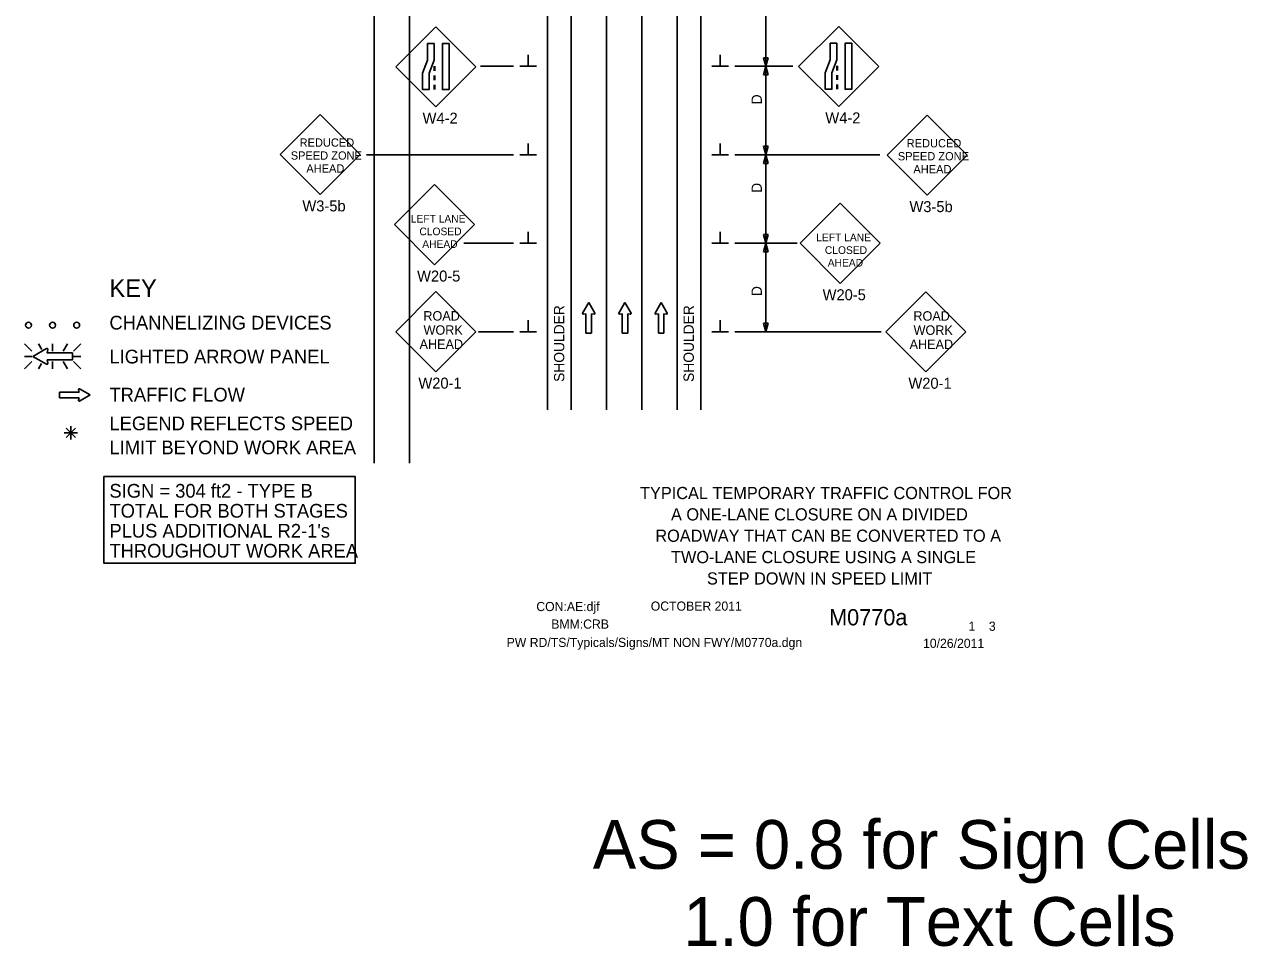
# Model space of a CAD drawing. Extents: x 16744 to 19504, y 5731 to 6974.
# Drawn here: x 16744 to 17573, y 5731 to 6356 of the extents above; entities that cross this region are included whole.
import ezdxf

# ---------------------------------------------------------------- set-up
doc = ezdxf.new("R2010")
doc.units = 0
for name, color, linetype in [('ALI_LEGAL_EX', 7, 'Continuous'), ('BORDER', 7, 'Continuous'), ('BORDER_SIGNAL_WO', 7, 'Continuous'), ('MT_SCRATCH_LEVEL_E', 7, 'Continuous'), ('PAVT_EDGE_EX', 7, 'Continuous'), ('TRAFFIC_SIGNS_PR', 7, 'Continuous'), ('TYPICAL_TEXT_DIMEN_EX', 7, 'Continuous'), ('TYPICAL_TEXT_DIMEN_PR', 7, 'Continuous')]:
    doc.layers.add(name, color=color, linetype=linetype)

msp = doc.modelspace()

# ---------------------------------------------------------------- linework, layer by layer
at = {"layer": 'ALI_LEGAL_EX'}
for p, q in [((16980.68, 6974.12), (16980.68, 6155.98)), ((17004.68, 6974.12), (17004.68, 6155.98)), ((16980.68, 6922.21), (16980.68, 6058.3)), ((17004.68, 6922.21), (17004.68, 6058.3)), ((17138.25, 6923.7), (17138.25, 6094.51)), ((17162.25, 6923.7), (17162.25, 6094.51))]:
    msp.add_line(p, q, dxfattribs=at)
for points in [[(17138.25, 6323.7), (17138.25, 6298.7)], [(17162.25, 6323.7), (17162.25, 6298.7)], [(17138.25, 6223.7), (17138.25, 6198.7)], [(17162.25, 6223.7), (17162.25, 6198.7)], [(17138.25, 6098.7), (17138.25, 6123.7)], [(17138.25, 6098.7), (17138.25, 6123.7)], [(17162.25, 6123.7), (17162.25, 6098.7)]]:
    msp.add_lwpolyline(points, dxfattribs=at)
at = {"layer": 'MT_SCRATCH_LEVEL_E'}
for p, q in [((17126.22, 6167.34), (17122.11, 6160.1)), ((17126.22, 6167.34), (17122.11, 6160.1)), ((17130.37, 6160.1), (17126.22, 6167.34)), ((17130.37, 6160.1), (17126.22, 6167.34)), ((17150.78, 6167.34), (17146.67, 6160.1)), ((17150.78, 6167.34), (17146.67, 6160.1)), ((17154.92, 6160.1), (17150.78, 6167.34)), ((17154.92, 6160.1), (17150.78, 6167.34)), ((17175.34, 6167.34), (17171.22, 6160.1)), ((17175.34, 6167.34), (17171.22, 6160.1)), ((17179.48, 6160.1), (17175.34, 6167.34)), ((17179.48, 6160.1), (17175.34, 6167.34)), ((17122.59, 6159.41), (17124.37, 6159.73)), ((17122.59, 6159.41), (17124.37, 6159.73)), ((17124.37, 6159.73), (17124.37, 6146.47)), ((17124.37, 6159.73), (17124.37, 6146.47)), ((17128.11, 6146.47), (17128.11, 6159.73)), ((17128.11, 6159.73), (17129.89, 6159.41)), ((17128.11, 6146.47), (17128.11, 6159.73)), ((17128.11, 6159.73), (17129.89, 6159.41)), ((17147.15, 6159.41), (17148.92, 6159.73)), ((17147.15, 6159.41), (17148.92, 6159.73)), ((17148.92, 6159.73), (17148.92, 6146.47)), ((17148.92, 6159.73), (17148.92, 6146.47)), ((17152.67, 6146.47), (17152.67, 6159.73)), ((17152.67, 6159.73), (17154.44, 6159.41)), ((17152.67, 6146.47), (17152.67, 6159.73)), ((17152.67, 6159.73), (17154.44, 6159.41)), ((17171.71, 6159.41), (17173.48, 6159.73)), ((17171.71, 6159.41), (17173.48, 6159.73)), ((17173.48, 6159.73), (17173.48, 6146.47)), ((17173.48, 6159.73), (17173.48, 6146.47)), ((17177.23, 6146.47), (17177.23, 6159.73)), ((17177.23, 6159.73), (17179, 6159.41)), ((17177.23, 6146.47), (17177.23, 6159.73)), ((17177.23, 6159.73), (17179, 6159.41)), ((17124.37, 6146.47), (17128.11, 6146.47)), ((17124.37, 6146.47), (17128.11, 6146.47)), ((17148.92, 6146.47), (17152.67, 6146.47)), ((17148.92, 6146.47), (17152.67, 6146.47)), ((17173.48, 6146.47), (17177.23, 6146.47)), ((17173.48, 6146.47), (17177.23, 6146.47)), ((16780.63, 6106.49), (16767.37, 6106.49)), ((16767.37, 6106.49), (16767.37, 6102.75)), ((16780.63, 6106.49), (16767.37, 6106.49)), ((16767.37, 6106.49), (16767.37, 6102.75)), ((16780.31, 6108.27), (16780.63, 6106.49)), ((16780.31, 6108.27), (16780.63, 6106.49)), ((16788.24, 6104.64), (16780.99, 6108.75)), ((16788.24, 6104.64), (16780.99, 6108.75)), ((16780.99, 6100.49), (16788.24, 6104.64)), ((16780.99, 6100.49), (16788.24, 6104.64)), ((16767.37, 6102.75), (16780.63, 6102.75)), ((16767.37, 6102.75), (16780.63, 6102.75)), ((16780.63, 6102.75), (16780.31, 6100.97)), ((16780.63, 6102.75), (16780.31, 6100.97))]:
    msp.add_line(p, q, dxfattribs=at)
for centre, start, end in [((17122.51, 6159.87), 150.42484, 279.96381), ((17122.51, 6159.87), 150.42484, 279.96381), ((17129.96, 6159.87), 260.03619, 29.77312), ((17129.96, 6159.87), 260.03619, 29.77312), ((17147.07, 6159.87), 150.42484, 279.96381), ((17147.07, 6159.87), 150.42484, 279.96381), ((17154.51, 6159.87), 260.03619, 29.77312), ((17154.51, 6159.87), 260.03619, 29.77312), ((17171.63, 6159.87), 150.42484, 279.96381), ((17171.63, 6159.87), 150.42484, 279.96381), ((17179.07, 6159.87), 260.03619, 29.77312), ((17179.07, 6159.87), 260.03619, 29.77312), ((16780.77, 6108.34), 60.42484, 189.96381), ((16780.77, 6108.34), 60.42484, 189.96381), ((16780.77, 6100.9), 170.03619, 299.77312), ((16780.77, 6100.9), 170.03619, 299.77312)]:
    msp.add_arc(centre, 0.463, start, end, dxfattribs=at)
at = {"layer": 'PAVT_EDGE_EX'}
for p, q in [((17098.25, 6923.7), (17098.25, 6094.51)), ((17114.25, 6923.7), (17114.25, 6094.51)), ((17186.25, 6923.7), (17186.25, 6094.51)), ((17202.25, 6923.7), (17202.25, 6094.51))]:
    msp.add_line(p, q, dxfattribs=at)
at = {"layer": 'TRAFFIC_SIGNS_PR'}
for p, q in [((17022.62, 6354.32), (16995.47, 6327.17)), ((17049.78, 6327.17), (17022.62, 6354.32)), ((17295.73, 6354.51), (17268.58, 6327.36)), ((17322.88, 6327.36), (17295.73, 6354.51)), ((16995.47, 6327.17), (17022.62, 6300.02)), ((17021.38, 6327.66), (17021.38, 6324.46)), ((17021.38, 6321.26), (17021.38, 6318.06)), ((17021.78, 6327.66), (17021.78, 6324.46)), ((17021.78, 6321.26), (17021.78, 6318.06)), ((17022.62, 6300.02), (17049.78, 6327.17)), ((17268.58, 6327.36), (17295.73, 6300.2)), ((17294.48, 6327.85), (17294.48, 6324.65)), ((17294.48, 6321.45), (17294.48, 6318.25)), ((17294.88, 6327.85), (17294.88, 6324.65)), ((17294.88, 6321.45), (17294.88, 6318.25)), ((17295.73, 6300.2), (17322.88, 6327.36)), ((17021.38, 6314.86), (17021.38, 6311.66)), ((17021.78, 6314.86), (17021.78, 6311.66)), ((17294.48, 6315.05), (17294.48, 6311.85)), ((17294.88, 6315.05), (17294.88, 6311.85)), ((16944.12, 6294.81), (16916.97, 6267.66)), ((16971.27, 6267.66), (16944.12, 6294.81)), ((17355.79, 6294.33), (17328.63, 6267.18)), ((17382.94, 6267.18), (17355.79, 6294.33)), ((16916.97, 6267.66), (16944.12, 6240.5)), ((16944.12, 6240.5), (16971.27, 6267.66)), ((17328.63, 6267.18), (17355.79, 6240.02)), ((17355.79, 6240.02), (17382.94, 6267.18)), ((17021.7, 6247.26), (16994.55, 6220.1)), ((17048.85, 6220.1), (17021.7, 6247.26)), ((17296.66, 6234.59), (17269.51, 6207.44)), ((17323.82, 6207.44), (17296.66, 6234.59)), ((16994.55, 6220.1), (17021.7, 6192.95)), ((17021.7, 6192.95), (17048.85, 6220.1)), ((17269.51, 6207.44), (17296.66, 6180.28)), ((17296.66, 6180.28), (17323.82, 6207.44)), ((17022.57, 6174.66), (16995.42, 6147.51)), ((17049.72, 6147.51), (17022.57, 6174.66)), ((17354.86, 6174.59), (17327.71, 6147.44)), ((17382.01, 6147.44), (17354.86, 6174.59)), ((16995.42, 6147.51), (17022.57, 6120.36)), ((17022.57, 6120.36), (17049.72, 6147.51)), ((17327.71, 6147.44), (17354.86, 6120.28)), ((17354.86, 6120.28), (17382.01, 6147.44)), ((16743.6, 6139.28), (16748.53, 6134.35)), ((16755.36, 6135.46), (16753.16, 6139.29)), ((16762.68, 6134.35), (16762.68, 6139.29)), ((16769.92, 6134.35), (16772.77, 6139.29)), ((16776.83, 6134.35), (16781.77, 6139.29)), ((16748.53, 6130.8), (16743.6, 6130.8)), ((16776.83, 6130.8), (16781.77, 6130.8)), ((16743.6, 6122.31), (16748.53, 6127.24)), ((16753.11, 6122.3), (16755.22, 6125.97)), ((16762.68, 6127.24), (16762.68, 6122.3)), ((16772.81, 6122.3), (16769.96, 6127.24)), ((16776.83, 6127.24), (16781.77, 6122.3))]:
    msp.add_line(p, q, dxfattribs=at)
for points in [[(17021.38, 6342.91), (17021.38, 6331.73), (17018.03, 6322.84), (17018.03, 6311.66), (17013.54, 6311.66), (17013.54, 6322.84), (17016.88, 6331.73), (17016.88, 6342.91)], [(17031.51, 6342.91), (17031.51, 6311.66), (17027.02, 6311.66), (17027.02, 6342.91)], [(17294.48, 6343.09), (17294.48, 6331.91), (17291.14, 6323.03), (17291.14, 6311.85), (17286.64, 6311.85), (17286.64, 6323.03), (17289.99, 6331.91), (17289.99, 6343.09)], [(17304.62, 6343.09), (17304.62, 6311.85), (17300.13, 6311.85), (17300.13, 6343.09)]]:
    msp.add_lwpolyline(points, close=True, dxfattribs=at)
for points in [[(16758.61, 6136.07), (16749.32, 6130.8), (16758.61, 6125.47)], [(16759.49, 6126.1), (16759.08, 6128.37), (16776.1, 6128.37), (16776.1, 6133.17), (16759.08, 6133.17), (16759.49, 6135.45)]]:
    msp.add_lwpolyline(points, dxfattribs=at)
for centre in [(16746.39, 6151.91), (16762.69, 6151.91), (16778.99, 6151.91)]:
    msp.add_circle(centre, 2, dxfattribs=at)
for centre, radius, start, end in [((16758.9, 6135.55), 0.598, 350.73078, 118.89165), ((16758.9, 6126), 0.597, 241.48329, 9.95933)]:
    msp.add_arc(centre, radius, start, end, dxfattribs=at)
at = {"layer": 'TYPICAL_TEXT_DIMEN_EX'}
for p, q in [((16771.9, 6082.11), (16778.28, 6075.74)), ((16778.28, 6082.11), (16771.9, 6075.74)), ((16775.09, 6078.93), (16775.09, 6083.38)), ((16775.09, 6078.93), (16770.56, 6078.93)), ((16775.09, 6078.93), (16778.28, 6078.93)), ((16775.09, 6078.93), (16779.57, 6078.93)), ((16775.09, 6078.93), (16775.09, 6074.43))]:
    msp.add_line(p, q, dxfattribs=at)
msp.add_lwpolyline([(16797.51, 6049.21), (16967.87, 6049.21), (16967.87, 5990.46), (16797.51, 5990.46)], close=True, dxfattribs=at)
at = {"layer": 'TYPICAL_TEXT_DIMEN_PR'}
for p, q in [((17246.25, 6387.44), (17246.25, 6327.44)), ((17085.12, 6327.44), (17085.12, 6335.22)), ((17215.38, 6327.44), (17215.38, 6335.22)), ((17246.25, 6327.44), (17244.68, 6333.3)), ((17244.68, 6333.3), (17246.25, 6333.3)), ((17246.25, 6327.44), (17244.68, 6333.3)), ((17244.68, 6333.3), (17246.25, 6333.3)), ((17246.25, 6333.3), (17247.82, 6333.3)), ((17247.82, 6333.3), (17246.25, 6327.44)), ((17246.25, 6333.3), (17247.82, 6333.3)), ((17247.82, 6333.3), (17246.25, 6327.44)), ((17052.86, 6327.44), (17075.25, 6327.44)), ((17079.5, 6327.44), (17090.75, 6327.44)), ((17221, 6327.44), (17209.75, 6327.44)), ((17264.55, 6327.44), (17225.25, 6327.44)), ((17244.68, 6321.57), (17246.25, 6327.44)), ((17246.25, 6321.57), (17244.68, 6321.57)), ((17246.25, 6327.44), (17246.25, 6267.44)), ((17246.25, 6327.44), (17247.82, 6321.57)), ((17247.82, 6321.57), (17246.25, 6321.57)), ((17085.12, 6267.44), (17085.12, 6275.22)), ((17215.38, 6267.44), (17215.38, 6275.22)), ((17246.25, 6267.44), (17244.68, 6273.3)), ((17244.68, 6273.3), (17246.25, 6273.3)), ((17246.25, 6273.3), (17247.82, 6273.3)), ((17247.82, 6273.3), (17246.25, 6267.44)), ((16975.6, 6267.44), (17075.25, 6267.44)), ((17079.5, 6267.44), (17090.75, 6267.44)), ((17221, 6267.44), (17209.75, 6267.44)), ((17323.57, 6267.44), (17225.25, 6267.44)), ((17244.68, 6261.57), (17246.25, 6267.44)), ((17244.68, 6261.57), (17246.25, 6267.44)), ((17246.25, 6267.44), (17246.25, 6207.44)), ((17246.25, 6267.44), (17247.82, 6261.57)), ((17246.25, 6267.44), (17247.82, 6261.57)), ((17246.25, 6261.57), (17244.68, 6261.57)), ((17246.25, 6261.57), (17244.68, 6261.57)), ((17247.82, 6261.57), (17246.25, 6261.57)), ((17247.82, 6261.57), (17246.25, 6261.57)), ((17085.12, 6207.44), (17085.12, 6215.22)), ((17215.38, 6207.44), (17215.38, 6215.22)), ((17246.25, 6207.44), (17244.68, 6213.3)), ((17244.68, 6213.3), (17246.25, 6213.3)), ((17246.25, 6207.44), (17244.68, 6213.3)), ((17244.68, 6213.3), (17246.25, 6213.3)), ((17246.25, 6213.3), (17247.82, 6213.3)), ((17247.82, 6213.3), (17246.25, 6207.44)), ((17246.25, 6213.3), (17247.82, 6213.3)), ((17247.82, 6213.3), (17246.25, 6207.44)), ((17041.57, 6207.44), (17075.25, 6207.44)), ((17079.5, 6207.44), (17090.75, 6207.44)), ((17221, 6207.44), (17209.75, 6207.44)), ((17267.65, 6207.44), (17225.25, 6207.44)), ((17244.68, 6201.57), (17246.25, 6207.44)), ((17246.25, 6207.44), (17246.25, 6147.44)), ((17246.25, 6207.44), (17247.82, 6201.57)), ((17246.25, 6201.57), (17244.68, 6201.57)), ((17247.82, 6201.57), (17246.25, 6201.57)), ((17085.12, 6147.44), (17085.12, 6155.22)), ((17215.38, 6147.44), (17215.38, 6155.22)), ((17051.43, 6147.44), (17075.25, 6147.44)), ((17079.5, 6147.44), (17090.75, 6147.44)), ((17221, 6147.44), (17209.75, 6147.44)), ((17324.47, 6147.44), (17225.25, 6147.44)), ((17246.25, 6147.44), (17244.68, 6153.3)), ((17244.68, 6153.3), (17246.25, 6153.3)), ((17246.25, 6153.3), (17247.82, 6153.3)), ((17247.82, 6153.3), (17246.25, 6147.44))]:
    msp.add_line(p, q, dxfattribs=at)

# ---------------------------------------------------------------- texts
at = {"layer": 'BORDER'}
for s, p in [('TYPICAL TEMPORARY TRAFFIC CONTROL FOR', (17161.04, 6033.99)), ('A ONE-LANE CLOSURE ON A DIVIDED', (17182.02, 6019.51)), ('ROADWAY THAT CAN BE CONVERTED TO A', (17171.42, 6005.04)), ('TWO-LANE CLOSURE USING A SINGLE', (17182.06, 5990.56)), ('STEP DOWN IN SPEED LIMIT', (17206.42, 5976.08))]:
    msp.add_text(s, height=8.2598, dxfattribs=at).set_placement(p)
at = {"layer": 'BORDER_SIGNAL_WO'}
for s, height, p in [('CON:AE:djf', 6.2, (17090.69, 5958.06)), ('    OCTOBER 2011    ', 6.2, (17159.08, 5958.34)), ('    M0770a   ', 11, (17272.86, 5948.38)), ('BMM:CRB   ', 6.2, (17100.81, 5946.17)), (' 1    3 ', 6.2, (17381.45, 5944.7)), ('PW RD/TS/Typicals/Signs/MT NON FWY/M0770a.dgn    ', 6.2, (17070.55, 5933.71)), ('10/26/2011    ', 6.2, (17352.93, 5933.13)), ('AS = 0.8 for Sign Cells', 33.0301, (17128.99, 5783.31)), ('     1.0 for Text Cells', 33.0301, (17128.99, 5731.08))]:
    msp.add_text(s, height=height, dxfattribs=at).set_placement(p)
at = {"layer": 'TRAFFIC_SIGNS_PR'}
for s, height, p in [('W4-2', 7.44, (17013.58, 6288.58)), ('W4-2', 7.44, (17286.69, 6288.77)), ('REDUCED', 5.6, (16930.18, 6272.96)), ('REDUCED', 5.6, (17341.84, 6272.48)), ('SPEED ZONE', 5.6, (16924.17, 6264.16)), ('SPEED ZONE', 5.6, (17335.84, 6263.68)), ('AHEAD', 5.6, (16934.73, 6255.36)), ('AHEAD', 5.6, (17346.4, 6254.88)), ('W3-5b', 7.44, (16932.08, 6229.06)), ('W3-5b', 7.44, (17343.74, 6228.58)), ('LEFT LANE', 5.2, (17005.58, 6221.5)), ('CLOSED', 5.2, (17011.41, 6212.9)), ('LEFT LANE', 5.2, (17280.54, 6208.83)), ('AHEAD', 5.2, (17013.36, 6204.3)), ('CLOSED', 5.2, (17286.38, 6200.23)), ('AHEAD', 5.2, (17288.32, 6191.63)), ('W20-5', 7.44, (17009.87, 6181.51)), ('W20-5', 7.44, (17284.84, 6168.84)), ('ROAD', 6.4, (17014.11, 6155.04)), ('ROAD', 6.4, (17346.4, 6154.97)), ('WORK', 6.4, (17014.22, 6145.44)), ('WORK', 6.4, (17346.51, 6145.37)), ('AHEAD', 6.4, (17011.53, 6135.84)), ('AHEAD', 6.4, (17343.82, 6135.77)), ('W20-1', 7.44, (17010.74, 6108.92)), ('W20-1', 7.44, (17343.03, 6108.84))]:
    msp.add_text(s, height=height, dxfattribs=at).set_placement(p)
at = {"layer": 'TYPICAL_TEXT_DIMEN_EX'}
for s, height, p in [('KEY', 12, (16801.23, 6171.02)), ('CHANNELIZING DEVICES', 9.3, (16801.23, 6148.97)), ('LIGHTED ARROW PANEL', 9.3, (16801.23, 6125.97)), ('TRAFFIC FLOW', 9.3, (16801.23, 6100.17)), ('LEGEND REFLECTS SPEED', 9.3, (16801.23, 6080.67)), ('LIMIT BEYOND WORK AREA', 9.3, (16801.23, 6064.37)), ('SIGN = 304 ft2 - TYPE B', 9.3, (16801.23, 6034.97)), ('TOTAL FOR BOTH STAGES', 9.3, (16801.23, 6021.42)), ("PLUS ADDITIONAL R2-1's", 9.3, (16801.23, 6007.87)), ('THROUGHOUT WORK AREA', 9.3, (16801.23, 5994.32))]:
    msp.add_text(s, height=height, dxfattribs=at).set_placement(p)
at = {"layer": 'TYPICAL_TEXT_DIMEN_PR'}
for s, p in [('D', (17243.69, 6301.66)), ('D', (17243.69, 6241.66)), ('D', (17243.69, 6171.66)), ('SHOULDER', (17109.67, 6113.45)), ('SHOULDER', (17197.53, 6113.45))]:
    msp.add_text(s, height=7, rotation=90, dxfattribs=at).set_placement(p)

doc.saveas('drawing.dxf')
